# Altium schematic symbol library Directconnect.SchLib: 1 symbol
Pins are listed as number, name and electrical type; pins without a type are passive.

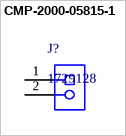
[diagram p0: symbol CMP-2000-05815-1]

## CMP-2000-05815-1
designator J?, comment 1729128
PCB Terminal Block, 13.5 A, 400 V, 2-Pin THD, RoHS, Bulk; Manufacturer: Phoenix Contact; Package Version: 03/2015; No. of Rows: 1; Pitch: 5.08mm; No. of Positions: 2; Voltage Rating: 400V; Current Rating: 13500mA
footprint PHOE-1729128-2_V (Receptacle, 2-Leads, Body 8.1x10.16mm, Pitch 5.08mm)
pins: 1, 2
